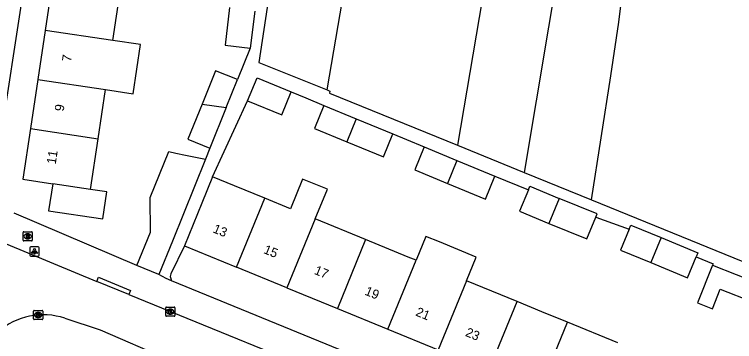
# Model space of a CAD drawing. Extents: x 163010 to 163853, y 382793 to 383982.
# Drawn here: x 163538.3 to 163616.5, y 383121.3 to 383156.8 of the extents above; entities that cross this region are included whole.
import ezdxf

# ---------------------------------------------------------------- set-up
doc = ezdxf.new("R2010")
doc.units = 0
for name, color, linetype in [('IMGEO_Brandkraan', 7, 'Continuous'), ('IMGEO_Kolk', 7, 'Continuous'), ('IMGEO_Lichtpunt', 7, 'Continuous'), ('IMGEO_Pand', 7, 'Continuous'), ('IMGEO_Pand_nummerreeks', 7, 'Continuous'), ('IMGEO_Rijbaan_lokaal_open', 7, 'Continuous'), ('IMGEO_Voetpad_open', 7, 'Continuous')]:
    doc.layers.add(name, color=color, linetype=linetype)

msp = doc.modelspace()

# ---------------------------------------------------------------- linework, layer by layer
at = {"layer": 'IMGEO_Brandkraan'}
for p, q in [((163539.312, 383133.217), (163540.164, 383133.217)), ((163539.237, 383132.291), (163539.237, 383133.143)), ((163539.748, 383132.437), (163539.723, 383132.437)), ((163539.725, 383132.997), (163539.75, 383132.997)), ((163540.238, 383133.143), (163540.238, 383132.291)), ((163540.164, 383132.217), (163539.312, 383132.217))]:
    msp.add_line(p, q, dxfattribs=at)
for points in [[(163539.312, 383133.217), (163540.164, 383133.217)], [(163539.237, 383132.291), (163539.237, 383133.143)], [(163539.585, 383132.917), (163539.585, 383132.517), (163539.798, 383132.517)], [(163539.816, 383132.917), (163539.585, 383132.917)], [(163539.764, 383132.836), (163539.71, 383132.836), (163539.71, 383132.76)], [(163539.71, 383132.76), (163539.763, 383132.76)], [(163539.772, 383132.684), (163539.71, 383132.684), (163539.71, 383132.603)], [(163539.71, 383132.603), (163539.772, 383132.603)], [(163540.238, 383133.143), (163540.238, 383132.291)], [(163540.164, 383132.217), (163539.312, 383132.217)]]:
    msp.add_lwpolyline(points, dxfattribs=at)
for centre, radius, start, end in [((163539.314, 383133.141), 0.0765, 91.55205, 178.44795), ((163539.314, 383133.141), 0.0765, 91.55205, 178.44795), ((163540.162, 383133.141), 0.0765, 1.55205, 88.44795), ((163540.162, 383133.141), 0.0765, 1.55205, 88.44795), ((163539.765, 383132.798), 0.0379, 267.82845, 90.93552), ((163539.773, 383132.643), 0.0404, 269.87594, 90.50774), ((163539.804, 383132.768), 0.251, 268.66757, 293.53466), ((163539.82, 383132.772), 0.145, 59.4692, 91.53667), ((163539.845, 383132.819), 0.0922, 285.51372, 58.15012), ((163539.85, 383132.627), 0.105, 301.31148, 78.98903), ((163539.314, 383132.293), 0.0765, 181.55205, 268.44795), ((163539.314, 383132.293), 0.0765, 181.55205, 268.44795), ((163540.162, 383132.293), 0.0765, 271.55205, 358.44795), ((163540.162, 383132.293), 0.0765, 271.55205, 358.44795)]:
    msp.add_arc(centre, radius, start, end, dxfattribs=at)
for centre, major_axis, ratio, start_param, end_param in [((163539.724, 383132.717), (-0.387, 0.002), 0.722429, 4.712389, 7.853982), ((163539.749, 383132.717), (-0.39, 0.002), 0.717154, 1.570796, 4.712389)]:
    msp.add_ellipse(centre, major_axis=major_axis, ratio=ratio, start_param=start_param, end_param=end_param, dxfattribs=at)
at = {"layer": 'IMGEO_Kolk'}
for p, q in [((163540.374, 383123.748), (163540.374, 383124.6)), ((163540.449, 383124.674), (163541.301, 383124.674)), ((163541.375, 383124.6), (163541.375, 383123.748)), ((163554.728, 383124.106), (163554.728, 383124.958)), ((163554.803, 383125.032), (163555.655, 383125.032)), ((163555.216, 383124.812), (163555.241, 383124.812)), ((163555.729, 383124.958), (163555.729, 383124.106)), ((163540.885, 383123.894), (163540.86, 383123.894)), ((163540.862, 383124.454), (163540.887, 383124.454)), ((163555.655, 383124.032), (163554.803, 383124.032)), ((163555.239, 383124.252), (163555.214, 383124.252)), ((163541.301, 383123.674), (163540.449, 383123.674))]:
    msp.add_line(p, q, dxfattribs=at)
for points in [[(163540.374, 383123.748), (163540.374, 383124.6)], [(163540.449, 383124.674), (163541.301, 383124.674)], [(163541.375, 383124.6), (163541.375, 383123.748)], [(163554.728, 383124.106), (163554.728, 383124.958)], [(163554.803, 383125.032), (163555.655, 383125.032)], [(163555.049, 383124.732), (163555.172, 383124.732), (163555.172, 383124.581), (163555.302, 383124.732), (163555.466, 383124.732), (163555.32, 383124.581), (163555.473, 383124.332), (163555.321, 383124.332), (163555.236, 383124.496), (163555.172, 383124.429), (163555.172, 383124.332), (163555.049, 383124.332), (163555.049, 383124.732)], [(163555.729, 383124.958), (163555.729, 383124.106)], [(163540.695, 383124.374), (163540.818, 383124.374), (163540.818, 383124.223), (163540.948, 383124.374), (163541.112, 383124.374), (163540.966, 383124.223), (163541.119, 383123.974), (163540.967, 383123.974), (163540.882, 383124.138), (163540.818, 383124.071), (163540.818, 383123.974), (163540.695, 383123.974), (163540.695, 383124.374)], [(163555.655, 383124.032), (163554.803, 383124.032)], [(163541.301, 383123.674), (163540.449, 383123.674)]]:
    msp.add_lwpolyline(points, dxfattribs=at)
for centre, start, end in [((163540.451, 383124.598), 91.55205, 178.44795), ((163540.451, 383124.598), 91.55205, 178.44795), ((163541.299, 383124.598), 1.55205, 88.44795), ((163541.299, 383124.598), 1.55205, 88.44795), ((163554.805, 383124.956), 91.55205, 178.44795), ((163554.805, 383124.956), 91.55205, 178.44795), ((163555.653, 383124.956), 1.55205, 88.44795), ((163555.653, 383124.956), 1.55205, 88.44795), ((163554.805, 383124.108), 181.55205, 268.44795), ((163554.805, 383124.108), 181.55205, 268.44795), ((163555.653, 383124.108), 271.55205, 358.44795), ((163555.653, 383124.108), 271.55205, 358.44795), ((163540.451, 383123.75), 181.55205, 268.44795), ((163540.451, 383123.75), 181.55205, 268.44795), ((163541.299, 383123.75), 271.55205, 358.44795), ((163541.299, 383123.75), 271.55205, 358.44795)]:
    msp.add_arc(centre, 0.0765, start, end, dxfattribs=at)
for centre, major_axis, ratio, start_param, end_param in [((163555.215, 383124.532), (-0.387, 0.002), 0.722429, 4.712389, 7.853982), ((163555.24, 383124.532), (-0.39, 0.002), 0.717154, 1.570796, 4.712389), ((163540.861, 383124.174), (-0.387, 0.002), 0.722429, 4.712389, 7.853982), ((163540.886, 383124.174), (-0.39, 0.002), 0.717154, 1.570796, 4.712389)]:
    msp.add_ellipse(centre, major_axis=major_axis, ratio=ratio, start_param=start_param, end_param=end_param, dxfattribs=at)
at = {"layer": 'IMGEO_Lichtpunt'}
for p, q in [((163539.978, 383131.481), (163539.978, 383130.674)), ((163539.978, 383131.481), (163539.978, 383130.674)), ((163540.88, 383131.576), (163540.072, 383131.576)), ((163540.88, 383131.576), (163540.072, 383131.576)), ((163540.974, 383130.674), (163540.974, 383131.481)), ((163540.974, 383130.674), (163540.974, 383131.481)), ((163540.072, 383130.58), (163540.88, 383130.58)), ((163540.072, 383130.58), (163540.88, 383130.58))]:
    msp.add_line(p, q, dxfattribs=at)
for points in [[(163540.352, 383131.145), (163540.391, 383131.117), (163540.203, 383130.855), (163540.165, 383130.882), (163540.352, 383131.145)], [(163540.454, 383131.097), (163540.501, 383131.097), (163540.501, 383130.775), (163540.454, 383130.775), (163540.454, 383131.097)], [(163540.564, 383131.117), (163540.602, 383131.144), (163540.789, 383130.882), (163540.75, 383130.854), (163540.564, 383131.117)]]:
    msp.add_lwpolyline(points, dxfattribs=at)
msp.add_circle((163540.477, 383131.279), 0.0994, dxfattribs=at)
for centre, start, end in [((163540.072, 383131.481), 90, 180), ((163540.072, 383131.481), 90, 180), ((163540.88, 383131.481), 0, 90), ((163540.88, 383131.481), 0, 90), ((163540.072, 383130.674), 180, 270), ((163540.072, 383130.674), 180, 270), ((163540.88, 383130.674), 270, 0), ((163540.88, 383130.674), 270, 360)]:
    msp.add_arc(centre, 0.0946, start, end, dxfattribs=at)
at = {"layer": 'IMGEO_Pand'}
for points in [[(163567.317, 383167.857), (163564.835, 383151.595), (163572.264, 383148.601)], [(163572.264, 383148.601), (163575.341, 383166.634)], [(163590.125, 383164.381), (163586.426, 383142.608)], [(163597.621, 383163.239), (163593.656, 383139.661)], [(163600.974, 383136.678), (163603.078, 383150.126), (163603.961, 383155.946), (163604.715, 383162.158)], [(163542.443, 383160.401), (163541.646, 383155.072)], [(163548.98, 383153.976), (163549.777, 383159.305)], [(163561.665, 383157.549), (163561.18, 383153.465), (163563.922, 383153.139)], [(163564.397, 383157.141), (163563.922, 383153.139)], [(163541.646, 383155.072), (163540.849, 383149.742)], [(163548.98, 383153.976), (163541.646, 383155.072)], [(163548.184, 383148.646), (163551.201, 383148.195), (163551.997, 383153.525), (163548.98, 383153.976)], [(163562.544, 383149.725), (163560.155, 383150.693), (163558.688, 383147.076)], [(163540.849, 383149.742), (163540.052, 383144.412)], [(163540.849, 383149.742), (163548.184, 383148.646)], [(163561.312, 383146.684), (163562.544, 383149.725)], [(163563.626, 383147.439), (163564.659, 383149.935), (163568.351, 383148.407)], [(163547.387, 383143.316), (163548.184, 383148.646)], [(163563.626, 383147.439), (163567.326, 383145.907), (163568.351, 383148.407)], [(163572.264, 383148.601), (163572.56, 383148.482), (163572.529, 383148.272), (163586.426, 383142.608)], [(163558.688, 383147.076), (163557.142, 383143.262), (163559.532, 383142.293)], [(163558.688, 383147.076), (163561.312, 383146.684)], [(163561.312, 383146.684), (163559.532, 383142.293)], [(163571.922, 383146.93), (163570.896, 383144.43), (163574.4, 383142.98)], [(163571.922, 383146.93), (163575.425, 383145.48)], [(163575.425, 383145.48), (163574.4, 383142.98)], [(163575.425, 383145.48), (163579.394, 383143.837)], [(163540.052, 383144.412), (163539.23, 383138.911), (163542.459, 383138.429)], [(163540.052, 383144.412), (163547.387, 383143.316)], [(163574.4, 383142.98), (163578.37, 383141.337), (163579.394, 383143.837)], [(163546.565, 383137.815), (163547.387, 383143.316)], [(163586.426, 383142.608), (163593.656, 383139.661)], [(163551.599, 383129.553), (163553.083, 383133.175), (163553.039, 383136.915), (163555.085, 383141.91), (163555.814, 383141.76), (163556.877, 383141.541), (163559.048, 383141.095)], [(163582.812, 383142.423), (163581.788, 383139.923), (163585.343, 383138.452)], [(163582.812, 383142.423), (163586.368, 383140.952)], [(163559.048, 383141.095), (163555.452, 383132.204), (163553.968, 383128.582)], [(163586.368, 383140.952), (163585.343, 383138.452)], [(163586.368, 383140.952), (163590.489, 383139.247)], [(163593.656, 383139.661), (163600.974, 383136.678)], [(163559.829, 383139.179), (163558.654, 383136.311), (163556.757, 383131.684)], [(163565.494, 383136.856), (163562.204, 383138.205), (163559.829, 383139.179)], [(163570.971, 383134.611), (163572.289, 383137.828), (163569.59, 383138.934), (163568.271, 383135.718), (163565.494, 383136.856)], [(163585.343, 383138.452), (163589.456, 383136.75), (163590.489, 383139.247)], [(163542.459, 383138.429), (163542.019, 383135.489), (163547.889, 383134.612), (163548.328, 383137.552), (163546.565, 383137.815)], [(163546.565, 383137.815), (163542.459, 383138.429)], [(163594.122, 383137.749), (163594.285, 383138.145), (163597.472, 383136.831)], [(163594.122, 383137.749), (163593.166, 383135.432), (163596.36, 383134.115)], [(163562.422, 383129.362), (163565.494, 383136.856)], [(163597.472, 383136.831), (163596.36, 383134.115)], [(163601.436, 383134.803), (163601.575, 383135.14), (163597.472, 383136.831)], [(163600.974, 383136.678), (163625.249, 383126.784)], [(163596.36, 383134.115), (163600.456, 383132.426), (163601.436, 383134.803)], [(163570.971, 383134.611), (163567.9, 383127.116)], [(163576.449, 383132.366), (163570.971, 383134.611)], [(163605.056, 383133.487), (163604.121, 383131.218), (163607.414, 383129.861)], [(163605.056, 383133.487), (163605.24, 383133.932), (163608.527, 383132.577)], [(163587.412, 383127.893), (163588.468, 383130.468), (163584.459, 383132.11), (163582.99, 383132.712), (163581.928, 383130.12)], [(163608.527, 383132.577), (163607.414, 383129.861)], [(163608.527, 383132.577), (163612.53, 383130.926), (163612.346, 383130.481)], [(163556.757, 383131.684), (163562.422, 383129.362)], [(163576.449, 383132.366), (163573.377, 383124.871)], [(163581.928, 383130.12), (163581.079, 383130.468), (163576.449, 383132.366)], [(163578.855, 383122.625), (163581.928, 383130.12)], [(163607.414, 383129.861), (163611.411, 383128.213), (163612.346, 383130.481)], [(163553.968, 383128.582), (163551.599, 383129.553)], [(163567.9, 383127.116), (163562.422, 383129.362)], [(163614.131, 383129.592), (163612.496, 383125.487), (163614.113, 383124.843), (163614.969, 383126.996), (163618.46, 383125.594)], [(163614.131, 383129.592), (163619.263, 383127.552)], [(163587.412, 383127.893), (163584.332, 383120.38)], [(163592.89, 383125.648), (163587.412, 383127.893)], [(163567.9, 383127.116), (163573.377, 383124.871)], [(163589.811, 383118.134), (163592.89, 383125.648)], [(163598.363, 383123.391), (163595.582, 383124.531), (163592.89, 383125.648)], [(163573.377, 383124.871), (163578.855, 383122.625)], [(163595.287, 383115.889), (163598.363, 383123.391)], [(163603.841, 383121.145), (163598.363, 383123.391)], [(163578.855, 383122.625), (163584.332, 383120.38)]]:
    msp.add_lwpolyline(points, dxfattribs=at)
at = {"layer": 'IMGEO_Rijbaan_lokaal_open'}
for points in [[(163537.399, 383131.89), (163547.235, 383127.815)], [(163550.724, 383126.385), (163547.235, 383127.815)], [(163550.724, 383126.385), (163576.095, 383116.039)], [(163543.777, 383123.82), (163547.625, 383122.548), (163554.966, 383119.373)]]:
    msp.add_lwpolyline(points, dxfattribs=at)
msp.add_arc((163541.438, 383116.736), 7.461, 71.72647, 131.23633, dxfattribs=at)
at = {"layer": 'IMGEO_Voetpad_open'}
for points in [[(163536.268, 383138.719), (163537.369, 383146.888), (163541.181, 383171.663)], [(163563.922, 383153.139), (163562.544, 383149.725)], [(163568.351, 383148.407), (163569.957, 383147.743), (163571.922, 383146.93)], [(163559.829, 383139.179), (163563.626, 383147.439)], [(163579.394, 383143.837), (163580.896, 383143.216), (163582.812, 383142.423)], [(163559.532, 383142.293), (163559.048, 383141.095)], [(163590.489, 383139.247), (163594.122, 383137.749)], [(163551.599, 383129.553), (163538.257, 383135.219)], [(163601.436, 383134.803), (163605.056, 383133.487)], [(163556.757, 383131.684), (163555.276, 383128.633), (163555.2, 383128.339), (163555.351, 383127.886)], [(163612.346, 383130.481), (163614.183, 383129.723), (163614.131, 383129.592)], [(163555.351, 383127.886), (163554.767, 383128.125), (163553.968, 383128.582)], [(163547.235, 383127.815), (163547.424, 383128.277), (163550.913, 383126.847), (163550.724, 383126.385)], [(163648.196, 383089.907), (163555.351, 383127.886)]]:
    msp.add_lwpolyline(points, dxfattribs=at)

# ---------------------------------------------------------------- texts
at = {"layer": 'IMGEO_Pand_nummerreeks'}
for s, rotation, p in [('7', 81.49775, (163544.446, 383151.621)), ('9', 81.49775, (163543.641, 383146.234)), ('11', 81.49752, (163542.785, 383140.505)), ('13', 337.71194, (163559.782, 383133.167)), ('15', 337.70983, (163565.283, 383130.912)), ('17', 337.70983, (163570.783, 383128.658)), ('19', 337.71194, (163576.282, 383126.403)), ('21', 337.71194, (163581.802, 383124.141)), ('23', 337.70983, (163587.199, 383121.928))]:
    msp.add_text(s, height=1, rotation=rotation, dxfattribs=at).set_placement(p)

doc.saveas('drawing.dxf')
